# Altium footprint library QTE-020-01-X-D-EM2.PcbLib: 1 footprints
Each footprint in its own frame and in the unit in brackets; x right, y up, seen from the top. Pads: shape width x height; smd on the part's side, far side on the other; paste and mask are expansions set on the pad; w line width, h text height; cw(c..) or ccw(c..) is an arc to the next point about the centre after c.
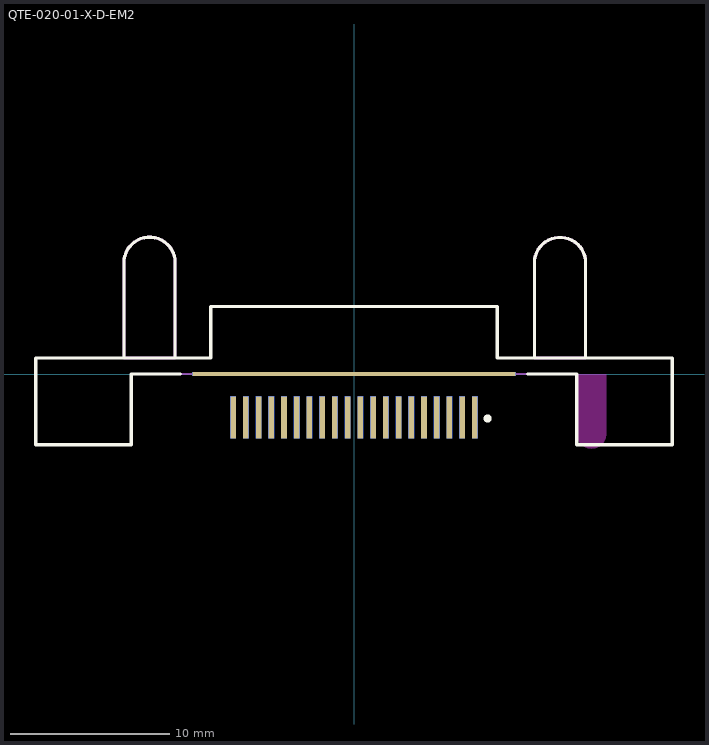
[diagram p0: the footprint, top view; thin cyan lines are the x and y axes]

## QTE-020-01-X-D-EM2 [mm] "0.80mm pitch, 40 pin, high speed terminal strip; w/edge mounts"
height 2.99
pads (42):
  rect 0.35x2.65 smd mask+0: 1(7.6,-2.725) 3(6.8,-2.725) 5(6,-2.725) 7(5.2,-2.725) 9(4.4,-2.725) 11(3.6,-2.725) 13(2.8,-2.725) 15(2,-2.725) 17(1.2,-2.725) 19(0.4,-2.725) 21(-0.4,-2.725) 23(-1.2,-2.725) 25(-2,-2.725) 27(-2.8,-2.725) 29(-3.6,-2.725) 31(-4.4,-2.725) 33(-5.2,-2.725) 35(-6,-2.725) 37(-6.8,-2.725) 39(-7.6,-2.725)
  rect 0.35x2.65 smd far side mask+0: 2(7.6,-2.725) 4(6.8,-2.725) 6(6,-2.725) 8(5.2,-2.725) 10(4.4,-2.725) 12(3.6,-2.725) 14(2.8,-2.725) 16(2,-2.725) 18(1.2,-2.725) 20(0.4,-2.725) 22(-0.4,-2.725) 24(-1.2,-2.725) 26(-2,-2.725) 28(-2.8,-2.725) 30(-3.6,-2.725) 32(-4.4,-2.725) 34(-5.2,-2.725) 36(-6,-2.725) 38(-6.8,-2.725) 40(-7.6,-2.725)
  rect 20.32x0.25 smd mask+0: 41(0,0)
  rect 20.32x0.25 smd far side mask+0: 42(0,0)
Top Overlay:
  circle w0.25: c8.4,-2.8 r0.125
  lines w0.2: -10.9,0 -14,0 -14,-4.45 -20,-4.45 -20,1 -9,1 -9,4.25 9,4.25 9,1 20,1 20,-4.45 14,-4.45 14,0 10.9,0 ; -14.45,1 -14.45,7.2 cw(c-12.85,6.989) -11.25,7.2 -11.25,1 -14.45,1 ; 11.35,1 11.35,7.2 cw(c12.95,6.975) 14.55,7.2 14.55,1 11.35,1
Top Paste:
  region: -10.16,0 10.16,0 10.16,-0.25 -10.16,-0.25
Bottom Paste:
  region: -10.16,0 10.16,0 10.16,-0.25 -10.16,-0.25
Top Solder:
  region: -10.16,0 10.16,0 10.16,-0.25 -10.16,-0.25
  region: -7.535,-4.05 -7.665,-4.05 -7.665,-2.851 -7.535,-2.851
  region: -6.735,-4.05 -6.865,-4.05 -6.865,-2.851 -6.735,-2.851
  region: -5.935,-4.05 -6.065,-4.05 -6.065,-2.851 -5.935,-2.851
  region: -5.135,-4.05 -5.265,-4.05 -5.265,-2.851 -5.135,-2.851
  region: -4.335,-4.05 -4.465,-4.05 -4.465,-2.851 -4.335,-2.851
  region: -3.535,-4.05 -3.665,-4.05 -3.665,-2.851 -3.535,-2.851
  region: -2.735,-4.05 -2.865,-4.05 -2.865,-2.851 -2.735,-2.851
  region: -1.935,-4.05 -2.065,-4.05 -2.065,-2.851 -1.935,-2.851
  region: -1.135,-4.05 -1.265,-4.05 -1.265,-2.851 -1.135,-2.851
  region: -0.335,-4.05 -0.465,-4.05 -0.465,-2.851 -0.335,-2.851
  region: 0.465,-4.05 0.335,-4.05 0.335,-2.851 0.465,-2.851
  region: 1.265,-4.05 1.135,-4.05 1.135,-2.851 1.265,-2.851
  region: 2.065,-4.05 1.935,-4.05 1.935,-2.851 2.065,-2.851
  region: 2.865,-4.05 2.735,-4.05 2.735,-2.851 2.865,-2.851
  region: 3.665,-4.05 3.535,-4.05 3.535,-2.851 3.665,-2.851
  region: 4.465,-4.05 4.335,-4.05 4.335,-2.851 4.465,-2.851
  region: 5.265,-4.05 5.135,-4.05 5.135,-2.851 5.265,-2.851
  region: 6.065,-4.05 5.935,-4.05 5.935,-2.851 6.065,-2.851
  region: 6.865,-4.05 6.735,-4.05 6.735,-2.851 6.865,-2.851
  region: 7.665,-4.05 7.535,-4.05 7.535,-2.851 7.665,-2.851
Bottom Solder:
  region: -10.16,0 10.16,0 10.16,-0.25 -10.16,-0.25
  region: -7.535,-4.05 -7.665,-4.05 -7.665,-2.851 -7.535,-2.851
  region: -6.735,-4.05 -6.865,-4.05 -6.865,-2.851 -6.735,-2.851
  region: -5.935,-4.05 -6.065,-4.05 -6.065,-2.851 -5.935,-2.851
  region: -5.135,-4.05 -5.265,-4.05 -5.265,-2.851 -5.135,-2.851
  region: -4.335,-4.05 -4.465,-4.05 -4.465,-2.851 -4.335,-2.851
  region: -3.535,-4.05 -3.665,-4.05 -3.665,-2.851 -3.535,-2.851
  region: -2.735,-4.05 -2.865,-4.05 -2.865,-2.851 -2.735,-2.851
  region: -1.935,-4.05 -2.065,-4.05 -2.065,-2.851 -1.935,-2.851
  region: -1.135,-4.05 -1.265,-4.05 -1.265,-2.851 -1.135,-2.851
  region: -0.335,-4.05 -0.465,-4.05 -0.465,-2.851 -0.335,-2.851
  region: 0.465,-4.05 0.335,-4.05 0.335,-2.851 0.465,-2.851
  region: 1.265,-4.05 1.135,-4.05 1.135,-2.851 1.265,-2.851
  region: 2.065,-4.05 1.935,-4.05 1.935,-2.851 2.065,-2.851
  region: 2.865,-4.05 2.735,-4.05 2.735,-2.851 2.865,-2.851
  region: 3.665,-4.05 3.535,-4.05 3.535,-2.851 3.665,-2.851
  region: 4.465,-4.05 4.335,-4.05 4.335,-2.851 4.465,-2.851
  region: 5.265,-4.05 5.135,-4.05 5.135,-2.851 5.265,-2.851
  region: 6.065,-4.05 5.935,-4.05 5.935,-2.851 6.065,-2.851
  region: 6.865,-4.05 6.735,-4.05 6.735,-2.851 6.865,-2.851
  region: 7.665,-4.05 7.535,-4.05 7.535,-2.851 7.665,-2.851
Keep-Out Layer:
  pour cut-out: 15.86,0 15.868,-3.773 15.836,-4.015 15.743,-4.24 15.594,-4.434 15.401,-4.583 15.175,-4.676 14.933,-4.708 14.691,-4.676 14.466,-4.583 14.272,-4.434 14.123,-4.24 14.03,-4.015 13.998,-3.773 14.006,-3.773 14.006,0
Mechanical 13:
  lines w0.1: -20,-4.45 -14,-4.45 -14,0 14,0 14,-4.45 20,-4.45 20,1 9,1 9,4.25 -9,4.25 -9,1 -20,1 -20,-4.45
  lines w0.2: -14.45,1 -14.45,7.2 cw(c-12.85,6.989) -11.25,7.2 -11.25,1 -14.45,1 ; 11.35,1 11.35,7.2 cw(c12.95,6.975) 14.55,7.2 14.55,1 11.35,1
  text ".Designator" at 0,0 h1.52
